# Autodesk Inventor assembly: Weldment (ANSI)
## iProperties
Length Units: 11272
Angle Units: 11286
Time Units: 11279
Mass Units: 11290
Length Display Precision: 3
Angle Display Precision: 2
Part Number: Weldment (ANSI)
Document SubType Name: Weldment
Created: 2002-06
Designer: smithga
Created: 2002-08
Control State: 0
Master: False
Shininess: 64.0
Angle Units: 11279
Time Units: 11290
Mass Units: 11286
Compacted: True
Density: 0.0
Volumn: 0.0
Area: 0.0
PropertySet Name: Model Information
